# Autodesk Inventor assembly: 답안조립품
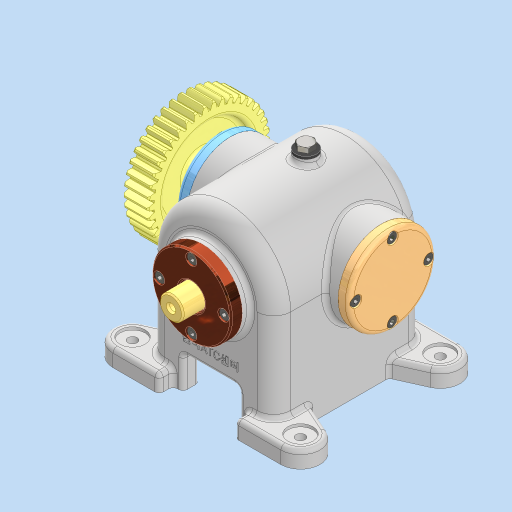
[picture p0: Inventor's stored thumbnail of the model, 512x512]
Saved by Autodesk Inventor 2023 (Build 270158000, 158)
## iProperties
Created: 2024-09
Part Number: 답안조립품
Document SubType Name: Assembly
Designer: asung
Author: asung
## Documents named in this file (17)
- C:\Users\asung\Desktop\740904V1008\답안조립품.iam
- C:\Users\asung\Desktop\740904V1008\본체.ipt
- C:\Users\asung\Desktop\740904V1008\앞커버.ipt
- C:\Users\asung\Desktop\740904V1008\뒷커버.ipt
- C:\Users\asung\Desktop\740904V1008\깊은 홈 볼베어링 6203.ipt
- C:\Users\asung\Desktop\740904V1008\편심축.ipt
- C:\Users\asung\Desktop\740904V1008\오일실 17 32 8.ipt
- C:\Users\asung\Desktop\740904V1008\육각 소켓 머리 볼트 M4x10.ipt
- C:\Users\asung\Desktop\740904V1008\부시.ipt
- C:\Users\asung\Desktop\740904V1008\로드.ipt
- C:\Users\asung\Desktop\740904V1008\실링 패드.ipt
- C:\Users\asung\Desktop\740904V1008\육각 머리 볼트 M6x0.75x12.ipt
- C:\Users\asung\Desktop\740904V1008\평행키 3x3x14.ipt
- C:\Users\asung\Desktop\740904V1008\스퍼 기어.ipt
- C:\Users\asung\Desktop\740904V1008\평와셔 M10.ipt
- C:\Users\asung\Desktop\740904V1008\스프링와셔 M10.ipt
- C:\Users\asung\Desktop\740904V1008\육각 너트 M10x1.ipt
